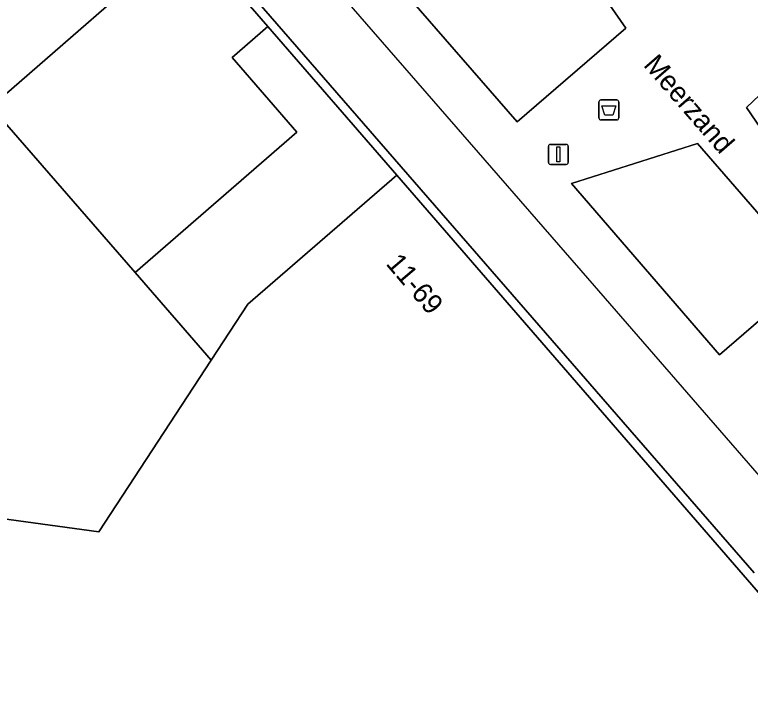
# Model space of a CAD drawing. Extents: x 155640 to 156811, y 382821 to 384049.
# Drawn here: x 156485.33 to 156522.06, y 383741.86 to 383776.01 of the extents above; entities that cross this region are included whole.
import ezdxf

# ---------------------------------------------------------------- set-up
doc = ezdxf.new("R2010")
doc.units = 0
for name, color, linetype in [('IMGEO_Afvalbak', 7, 'Continuous'), ('IMGEO_Groenvoorziening', 7, 'Continuous'), ('IMGEO_Lichtmast', 7, 'Continuous'), ('IMGEO_Lijnafwatering', 7, 'Continuous'), ('IMGEO_Muur', 7, 'Continuous'), ('IMGEO_Openbare_ruimte_label', 7, 'Continuous'), ('IMGEO_Pand', 7, 'Continuous'), ('IMGEO_Pand_nummerreeks', 7, 'Continuous'), ('IMGEO_Pand_overbouw', 7, 'Continuous'), ('IMGEO_Voetgangersgebied_open', 7, 'Continuous'), ('IMGEO_Voetpad_open', 7, 'Continuous')]:
    doc.layers.add(name, color=color, linetype=linetype)

msp = doc.modelspace()

# ---------------------------------------------------------------- linework, layer by layer
at = {"layer": 'IMGEO_Afvalbak'}
for p, q in [((156514.498, 383770.854), (156514.498, 383771.654)), ((156514.498, 383771.654), (156514.498, 383770.854)), ((156514.598, 383771.754), (156515.388, 383771.754)), ((156515.388, 383771.754), (156514.598, 383771.754)), ((156515.488, 383771.654), (156515.488, 383770.854)), ((156515.488, 383770.854), (156515.488, 383771.654)), ((156515.388, 383770.754), (156514.598, 383770.754)), ((156514.598, 383770.754), (156515.388, 383770.754))]:
    msp.add_line(p, q, dxfattribs=at)
msp.add_lwpolyline([(156514.641, 383771.468), (156515.345, 383771.468), (156515.196, 383770.998), (156514.79, 383770.998), (156514.641, 383771.468)], dxfattribs=at)
for centre, start, end in [((156514.598, 383771.654), 90, 180), ((156514.598, 383771.654), 90, 180), ((156515.388, 383771.654), 0, 90), ((156515.388, 383771.654), 360, 90), ((156514.598, 383770.854), 180, 270), ((156514.598, 383770.854), 180, 270), ((156515.388, 383770.854), 270, 0), ((156515.388, 383770.854), 270, 0)]:
    msp.add_arc(centre, 0.1, start, end, dxfattribs=at)
at = {"layer": 'IMGEO_Groenvoorziening'}
for points in [[(156515.843, 383775.339), (156509.534, 383784.434), (156502.001, 383780.354), (156510.412, 383770.654)], [(156530.378, 383766.154), (156526.321, 383775.6), (156521.87, 383771.375), (156527.144, 383763.648)], [(156525.131, 383762.997), (156519.416, 383769.575), (156513.128, 383767.581), (156520.512, 383759.022)]]:
    msp.add_lwpolyline(points, close=True, dxfattribs=at)
at = {"layer": 'IMGEO_Lichtmast'}
for p, q in [((156511.977, 383768.637), (156511.977, 383769.437)), ((156511.977, 383769.437), (156511.977, 383768.637)), ((156512.077, 383769.537), (156512.867, 383769.537)), ((156512.867, 383769.537), (156512.077, 383769.537)), ((156512.967, 383769.437), (156512.967, 383768.637)), ((156512.967, 383768.637), (156512.967, 383769.437)), ((156512.867, 383768.537), (156512.077, 383768.537)), ((156512.077, 383768.537), (156512.867, 383768.537))]:
    msp.add_line(p, q, dxfattribs=at)
msp.add_lwpolyline([(156512.397, 383769.412), (156512.547, 383769.412), (156512.547, 383768.662), (156512.397, 383768.662), (156512.397, 383769.412)], dxfattribs=at)
for centre, start, end in [((156512.077, 383769.437), 90, 180), ((156512.077, 383769.437), 90, 180), ((156512.867, 383769.437), 0, 90), ((156512.867, 383769.437), 360, 90), ((156512.077, 383768.637), 180, 270), ((156512.077, 383768.637), 180, 270), ((156512.867, 383768.637), 270, 0), ((156512.867, 383768.637), 270, 0)]:
    msp.add_arc(centre, 0.1, start, end, dxfattribs=at)
at = {"layer": 'IMGEO_Lijnafwatering'}
for points in [[(156513.947, 383762.849), (156501.468, 383777.231)], [(156526.359, 383748.544), (156513.947, 383762.849)]]:
    msp.add_lwpolyline(points, dxfattribs=at)
at = {"layer": 'IMGEO_Muur'}
msp.add_lwpolyline([(156497.967, 383775.43), (156504.403, 383768.001)], dxfattribs=at)
at = {"layer": 'IMGEO_Pand'}
msp.add_lwpolyline([(156497.967, 383775.43), (156494.004, 383780.006), (156484.378, 383771.622), (156484.208, 383771.362), (156484.606, 383770.903), (156491.34, 383763.141), (156499.415, 383770.147), (156496.178, 383773.878)], close=True, dxfattribs=at)
msp.add_lwpolyline([(156526.125, 383742.921), (156504.403, 383768.001), (156496.961, 383761.545), (156495.141, 383758.761), (156489.522, 383750.169), (156483.796, 383750.953), (156467.607, 383726.148), (156463.541, 383696.89), (156450.981, 383698.723), (156451.111, 383699.61), (156451.369, 383699.433), (156453.11, 383701.958), (156448.797, 383704.86), (156447.156, 383702.372), (156442.019, 383705.761), (156438.461, 383700.239), (156438.115, 383699.703), (156438.014, 383699.718), (156436.208, 383686.52)], dxfattribs=at)
at = {"layer": 'IMGEO_Pand_overbouw'}
msp.add_lwpolyline([(156522.244, 383748.131), (156489.331, 383786.036), (156489.254, 383786.124), (156477.703, 383776.08), (156477.589, 383775.981), (156481.391, 383771.435), (156483.001, 383769.51), (156484.606, 383770.903), (156484.208, 383771.362), (156484.378, 383771.622), (156494.004, 383780.006), (156497.967, 383775.43), (156496.178, 383773.878), (156499.415, 383770.147), (156491.34, 383763.141), (156495.141, 383758.761), (156496.961, 383761.545), (156504.403, 383768.001), (156526.125, 383742.921)], dxfattribs=at)
at = {"layer": 'IMGEO_Voetgangersgebied_open'}
msp.add_lwpolyline([(156499.367, 383804.6), (156473.48, 383782.1), (156463.557, 383793.358), (156460.001, 383788.093), (156471.098, 383780.883), (156477.589, 383775.981), (156477.703, 383776.08), (156489.254, 383786.124), (156489.331, 383786.036), (156522.244, 383748.131)], dxfattribs=at)
for points in [[(156515.843, 383775.339), (156510.412, 383770.654), (156502.001, 383780.354), (156509.534, 383784.434)], [(156527.144, 383763.648), (156521.87, 383771.375), (156526.321, 383775.6), (156530.378, 383766.154)], [(156520.512, 383759.022), (156513.128, 383767.581), (156519.416, 383769.575), (156525.131, 383762.997)]]:
    msp.add_lwpolyline(points, close=True, dxfattribs=at)
at = {"layer": 'IMGEO_Voetpad_open'}
msp.add_lwpolyline([(156522.244, 383748.131), (156489.331, 383786.036), (156489.254, 383786.124), (156477.703, 383776.08), (156477.589, 383775.981), (156481.391, 383771.435), (156483.001, 383769.51), (156484.208, 383771.362), (156484.378, 383771.622), (156494.004, 383780.006), (156497.967, 383775.43), (156504.403, 383768.001), (156526.125, 383742.921)], dxfattribs=at)
for points in [[(156504.403, 383768.001), (156497.967, 383775.43), (156496.178, 383773.878), (156499.415, 383770.147), (156491.34, 383763.141), (156495.141, 383758.761), (156496.961, 383761.545)], [(156443.341, 383707.811), (156442.019, 383705.761), (156447.156, 383702.372), (156448.797, 383704.86), (156453.11, 383701.958), (156451.369, 383699.433), (156451.111, 383699.61), (156450.981, 383698.723), (156463.541, 383696.89), (156467.607, 383726.148), (156483.796, 383750.953), (156489.522, 383750.169), (156495.141, 383758.761), (156491.34, 383763.141), (156484.606, 383770.903), (156483.001, 383769.51), (156475.806, 383758.471), (156482.61, 383754.028), (156484.681, 383752.675), (156454.756, 383706.822), (156452.619, 383708.217), (156445.881, 383712.618), (156442.937, 383708.11)]]:
    msp.add_lwpolyline(points, close=True, dxfattribs=at)

# ---------------------------------------------------------------- texts
at = {"layer": 'IMGEO_Openbare_ruimte_label'}
msp.add_text('Meerzand', height=1, rotation=310.9433, dxfattribs=at).set_placement((156516.684, 383773.481))
at = {"layer": 'IMGEO_Pand_nummerreeks'}
msp.add_text('11-69', height=1, rotation=310.4171, dxfattribs=at).set_placement((156503.824, 383763.554))

doc.saveas('drawing.dxf')
